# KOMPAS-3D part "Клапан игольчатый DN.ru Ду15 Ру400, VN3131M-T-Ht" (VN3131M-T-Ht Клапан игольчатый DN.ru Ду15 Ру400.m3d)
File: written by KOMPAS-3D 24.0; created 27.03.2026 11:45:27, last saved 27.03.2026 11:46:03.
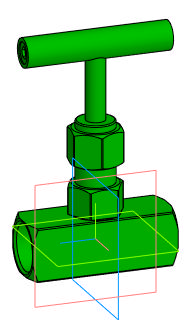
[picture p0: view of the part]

Document properties: Автор: Илья; Полное имя файла: D:\Обмен\Заказы с фриланса\DN.ru\VNxxM-T-Ht Клапан игольчатый DN.ru Ду8-50 Ру400\VN3131M-T-Ht Клапан игольчатый DN.ru Ду8-50 Ру400\DN15\VN3131M-T-Ht Клапан игольчатый DN.ru Ду15 Ру400.m3d

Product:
- Body: Body6  | qty 1
    Масса: 0.282571
- Part/product: Клапан игольчатый DN.ru Ду15 Ру400  | designation VN3131M-T-Ht
    Масса: 0.45
    Раздел спецификации: Прочие изделия
    Примечание: D090-02131

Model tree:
1. Body6  (labels: Body6)

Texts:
  VN3131M-T-Ht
